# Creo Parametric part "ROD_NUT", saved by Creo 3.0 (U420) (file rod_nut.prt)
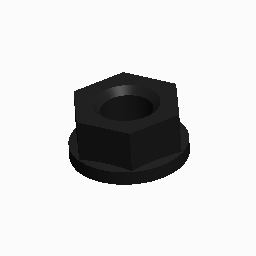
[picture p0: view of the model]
Units: millimeter Kilogram Sec (mmKs); MM, KILOGRAM, SECS

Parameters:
  MATERIAL = "35CrMo"

Created from: INLBS_PART_SOLID.PRT

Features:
  1. datum plane "SIDE", "RIGHT"
  2. datum plane "DTM1", "TOP"
  3. datum plane "DTM2", "FRONT"
  4. coordinate system "ORIGIN"
  5. datum axis "A_1"
  6. extrusion "Extrude 1"
  7. revolve "Revolve 1"
  8. hole "Hole 1"
  9. chamfer "Chamfer 1"
  10. datum point "CON_CAP_WELD"

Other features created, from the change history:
  group "COPIED_GROUP" (2 times)
  datum plane "SIDE"
  datum plane "DTM1"
  datum plane "DTM2"
  coordinate system "ORIGIN"
  revolve "Revolve 1"
  extrusion "Extrude 1"
  extruded cut "Extrude 2"
  extruded cut "Extrude 3"
  chamfer "Chamfer 1"
  datum point "CON_WELD"
  round "Round id 160"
